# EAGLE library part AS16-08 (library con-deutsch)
DEUTSCH Connector
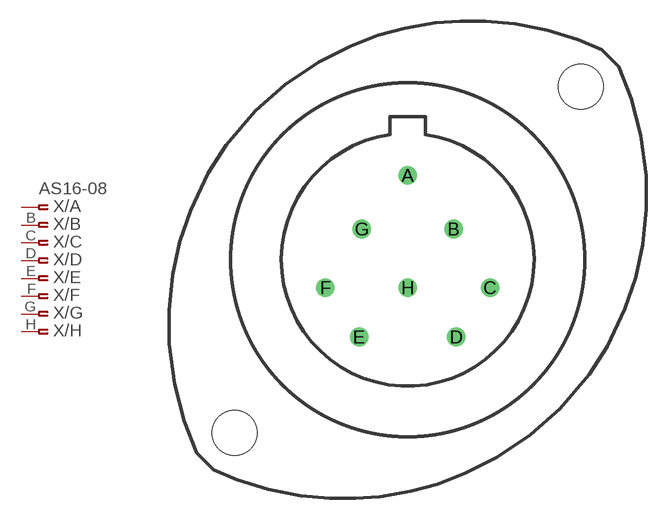
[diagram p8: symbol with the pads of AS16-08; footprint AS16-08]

Designator prefix X; gates /A=PINF_VAL /B=ASPINF /C=ASPINF /D=ASPINF /E=ASPINF /F=ASPINF /G=ASPINF /H=ASPINF

## AS16-08 (OC_FARNELL: unknown; OC_NEWARK: unknown)  [AS16-08]
A  /A:1  pas
B  /B:1  pas
C  /C:1  pas
D  /D:1  pas
E  /E:1  pas
F  /F:1  pas
G  /G:1  pas
H  /H:1  pas

## Footprint AS16-08 (pad centres in mm)
DEUTSCH Connector
drill 0.813 round: A 0,5.994; B 3.251,2.184; C 5.842,-1.981; D 3.454,-5.486; E -3.454,-5.486; F -5.842,-1.981; G -3.251,2.184; H 0,-1.981
hole 3.2 at 12.29,12.29
hole 3.2 at -12.29,-12.29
